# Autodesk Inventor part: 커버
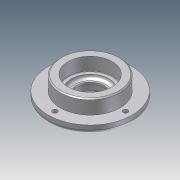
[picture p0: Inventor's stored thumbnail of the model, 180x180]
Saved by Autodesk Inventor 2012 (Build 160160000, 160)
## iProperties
Company: 한국ATC센터
Created: 2014-10
Part Number: 커버
Document SubType Name: Modeling
Designer: KYOUNG IL JANG
Density: 1 g/cm^3
Mass: 44.7286 g
Surface Area: 161.165 cm^2
Volume: 44.7286 cm^3
Material: 기본값
Author: KYOUNG IL JANG
Revision Number: 1
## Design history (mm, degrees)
sketch "스케치1"
  geometry: C1 r 38 at (0, 0); 1 further point
  constraints: 1 centre point, 1 coincident
  dimensions: "d0" = 76 diameter of C1
extrude "돌출1" new body sketch "스케치1" distance "d1" = 7; taper "d2" = 0 deg
sketch "스케치2"
  geometry: C1 r 27 at (0, 0); 1 further point
  constraints: 1 centre point, 1 coincident
  dimensions: "d3" = 54 diameter of C1
extrude "돌출2" join sketch "스케치2" distance "d4" = 13; taper "d5" = 0 deg
sketch "스케치3"
  geometry: C1 r 20 at (0, 0); 1 further point
  constraints: 1 centre point, 1 coincident
  dimensions: "d6" = 40 diameter of C1
extrude "돌출3" join sketch "스케치3" distance "d7" = 5; taper "d8" = 0 deg
hole "구멍1" diameter "d11" = 25; stored, may be unused: countersink angle "d15" = 90 deg, drill point angle "d17" = 118 deg; dims "d9" = 10, "d10" = 10, "d12" = 6, "d13" = 32, "d14" = 8.3, "d16" = 8
hole "구멍2" diameter "d20" = 34; stored, may be unused: countersink angle "d24" = 90 deg, drill point angle "d26" = 0 deg; dims "d18" = 10, "d19" = 10, "d21" = 6, "d22" = 40, "d23" = 12, "d25" = 3
fillet "모깎기2" dims "d34" = 3
fillet "모깎기1" dims "d27" = 0.3
chamfer "모따기1" distance "d28" = 1; stored, may be unused: second distance "d29" = 2, angle "d30" = 45 deg
chamfer "모따기2" distance "d31" = 1.2; stored, may be unused: second distance "d32" = 2, angle "d33" = 30 deg
sketch "스케치4" dims "d35" = 64
  geometry: 3 further points
  constraints: 2 horizontal alignment, 1 coincident, 2 other
hole "구멍3" sketch "스케치4" at (32, 0) diameter "d36" = 4.5; stored, may be unused: countersink angle "d40" = 90 deg, drill point angle "d42" = 118 deg; dims "d37" = 6, "d38" = 8, "d39" = 4.4, "d41" = 13
node "솔리드1"
pattern_circular "원형 패턴1" dims angle "d44" = 360 deg
